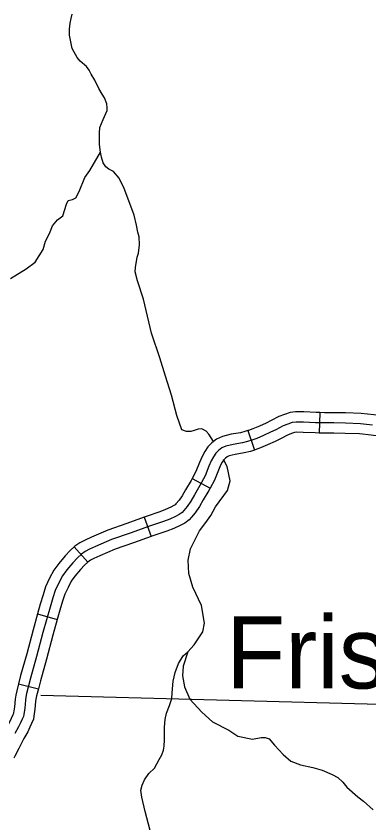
# Model space of a CAD drawing. Extents: x 670147 to 673275, y 705573 to 707613.
# Drawn here: x 672088.3 to 672139.9, y 706307.4 to 706425.4 of the extents above; entities that cross this region are included whole.
import ezdxf

# ---------------------------------------------------------------- set-up
doc = ezdxf.new("R2010")
doc.units = 0
for name, color, linetype in [('25', 7, 'Continuous'), ('32', 7, 'Continuous'), ('35', 7, 'Continuous'), ('5', 7, 'Continuous')]:
    doc.layers.add(name, color=color, linetype=linetype)

msp = doc.modelspace()

# ---------------------------------------------------------------- linework, layer by layer
at = {"layer": '32'}
for p, q in [((672132.75, 706367.45), (672132.66, 706364.45)), ((672122.22, 706364.81), (672123.19, 706361.97)), ((672114.05, 706357.79), (672116.69, 706356.37)), ((672107.06, 706352.14), (672108.06, 706349.31)), ((672096.83, 706347.82), (672098.83, 706345.58)), ((672091.44, 706338), (672094.33, 706337.19)), ((672088.67, 706327.77), (672091.58, 706327.04))]:
    msp.add_line(p, q, dxfattribs=at)
for points in [[(672132.75, 706367.45), (672132.2, 706367.47), (672130.43, 706367.56), (672129.19, 706367.57), (672128.39, 706367.46), (672127.56, 706367.19), (672126.75, 706366.87), (672125.63, 706366.27), (672124.91, 706365.92), (672123.9, 706365.46), (672122.96, 706365.08), (672122.3, 706364.83), (672122.22, 706364.81)], [(672143.39, 706366.76), (672142.99, 706366.8), (672142.06, 706366.91), (672140.66, 706367.1), (672138.79, 706367.32), (672136.52, 706367.41), (672134.82, 706367.43), (672133.44, 706367.43), (672132.75, 706367.45)], [(672140.47, 706365.61), (672138.68, 706365.82), (672136.48, 706365.91), (672134.81, 706365.93), (672133.41, 706365.93), (672132.13, 706365.97), (672130.38, 706366.06), (672129.28, 706366.07), (672128.72, 706365.99), (672128.07, 706365.78), (672127.39, 706365.51), (672126.3, 706364.93), (672125.55, 706364.57), (672124.5, 706364.08), (672123.51, 706363.68), (672122.8, 706363.42), (672122.19, 706363.21), (672121.41, 706363.04), (672120.07, 706362.8), (672119, 706362.54), (672118.42, 706362.28), (672117.94, 706361.92), (672117.54, 706361.49), (672117.18, 706360.98), (672116.87, 706360.4), (672116.53, 706359.59), (672115.96, 706358.18), (672115.21, 706356.79), (672114.39, 706355.42), (672113.88, 706354.5), (672113.33, 706353.69), (672112.83, 706353.14), (672112.59, 706352.85), (672112.19, 706352.56), (672111.65, 706352.27), (672110.78, 706351.87), (672109.87, 706351.51), (672107.82, 706350.82)], [(672122.22, 706364.81), (672121.79, 706364.66), (672121.12, 706364.51), (672119.76, 706364.27), (672118.51, 706363.97), (672117.65, 706363.58), (672116.93, 706363.04), (672116.37, 706362.43), (672115.91, 706361.76), (672115.52, 706361.05), (672115.14, 706360.16), (672114.6, 706358.82), (672114.05, 706357.79)], [(672132.66, 706364.45), (672132.07, 706364.47), (672130.33, 706364.56), (672129.38, 706364.57), (672129.05, 706364.52), (672128.58, 706364.37), (672128.02, 706364.15), (672126.98, 706363.6), (672126.19, 706363.21), (672125.1, 706362.71), (672124.05, 706362.28), (672123.31, 706362.01), (672123.19, 706361.97)], [(672143.07, 706363.78), (672142.66, 706363.82), (672141.68, 706363.93), (672140.28, 706364.13), (672138.56, 706364.33), (672136.45, 706364.41), (672134.81, 706364.43), (672133.39, 706364.43), (672132.66, 706364.45)], [(672123.19, 706361.97), (672122.59, 706361.76), (672121.7, 706361.57), (672120.38, 706361.34), (672119.49, 706361.12), (672119.2, 706360.99), (672118.95, 706360.8), (672118.71, 706360.54), (672118.46, 706360.19), (672118.22, 706359.75), (672117.92, 706359.02), (672117.32, 706357.54), (672116.69, 706356.37)], [(672114.05, 706357.79), (672113.91, 706357.53), (672113.09, 706356.17), (672112.6, 706355.29), (672112.15, 706354.62), (672111.69, 706354.11), (672111.56, 706353.95), (672111.4, 706353.84), (672110.97, 706353.61), (672110.19, 706353.25), (672109.36, 706352.92), (672107.33, 706352.24), (672107.06, 706352.14)], [(672116.69, 706356.37), (672116.52, 706356.05), (672115.69, 706354.67), (672115.16, 706353.72), (672114.52, 706352.77), (672113.97, 706352.16), (672113.63, 706351.74), (672112.98, 706351.28), (672112.32, 706350.93), (672111.37, 706350.49), (672110.38, 706350.1), (672108.31, 706349.4), (672108.06, 706349.31)], [(672107.06, 706352.14), (672104.51, 706351.23), (672101.74, 706350.26), (672099.35, 706349.22), (672098.41, 706348.81), (672097.64, 706348.42), (672096.92, 706347.9), (672096.83, 706347.82)], [(672107.82, 706350.82), (672105.01, 706349.82), (672102.29, 706348.86), (672099.95, 706347.85), (672099.05, 706347.46), (672098.43, 706347.14), (672097.86, 706346.72), (672097.28, 706346.22), (672096.6, 706345.48), (672095.74, 706344.43), (672095.12, 706343.59), (672094.56, 706342.56), (672094.04, 706341.43), (672093.69, 706340.33), (672093.28, 706338.99), (672092.24, 706335.26), (672091.32, 706331.76), (672090.43, 706328.61), (672089.86, 706326.37), (672089.74, 706325.83), (672089.67, 706325.37), (672089.58, 706324.22), (672089.44, 706323.3), (672089.39, 706323.01), (672089.21, 706322.6), (672088.96, 706322.06), (672088.69, 706321.47), (672088.12, 706320.5)], [(672108.06, 706349.31), (672105.51, 706348.4), (672102.83, 706347.47), (672100.55, 706346.47), (672099.69, 706346.1), (672099.21, 706345.86), (672098.8, 706345.55), (672098.83, 706345.58)], [(672096.83, 706347.82), (672096.23, 706347.29), (672095.47, 706346.47), (672094.55, 706345.35), (672093.85, 706344.39), (672093.22, 706343.23), (672092.64, 706341.97), (672092.26, 706340.78), (672091.84, 706339.41), (672091.44, 706338)], [(672098.83, 706345.58), (672098.33, 706345.14), (672097.73, 706344.5), (672096.93, 706343.51), (672096.39, 706342.79), (672095.91, 706341.88), (672095.44, 706340.88), (672095.12, 706339.88), (672094.72, 706338.57), (672094.33, 706337.19)], [(672091.44, 706338), (672090.79, 706335.66), (672089.87, 706332.16), (672088.98, 706329), (672088.67, 706327.77)], [(672094.33, 706337.19), (672093.69, 706334.87), (672092.77, 706331.37), (672091.88, 706328.23), (672091.58, 706327.04)], [(672088.67, 706327.77), (672088.41, 706326.73), (672088.26, 706326.1), (672088.18, 706325.53), (672088.09, 706324.4), (672087.95, 706323.54), (672087.94, 706323.44), (672087.84, 706323.21), (672087.6, 706322.69), (672087.36, 706322.17), (672086.8, 706321.21), (672086.03, 706319.67), (672085.46, 706318.57), (672085.3, 706318.26)], [(672091.58, 706327.04), (672091.32, 706326.02), (672091.21, 706325.55), (672091.17, 706325.2), (672091.07, 706324.05), (672090.92, 706323.06), (672090.84, 706322.59), (672090.58, 706321.99), (672090.32, 706321.43), (672090.02, 706320.77), (672089.44, 706319.79), (672088.71, 706318.31), (672088.13, 706317.2), (672087.97, 706316.89)]]:
    msp.add_lwpolyline(points, dxfattribs=at)
at = {"layer": '35'}
for points in [[(672117.17, 706363.22), (672116.52, 706364.3), (672116.14, 706364.73), (672115.5, 706365.07), (672114.94, 706365.03), (672114.38, 706364.85), (672113.87, 706364.68), (672113.23, 706364.68), (672112.58, 706364.94), (672111.85, 706367.01), (672111.04, 706370.01), (672110.18, 706372.79), (672109.33, 706375.45), (672108.13, 706379.05), (672106.97, 706384.06), (672106.07, 706386.72), (672105.73, 706388.05), (672105.77, 706388.67), (672106.03, 706390.19), (672106.2, 706390.79), (672106.37, 706391.98), (672106.33, 706393.17), (672106.11, 706393.86), (672105.94, 706394.85), (672105.6, 706396.35), (672104.96, 706398.06), (672104.1, 706400.21), (672103.37, 706401.74), (672102.58, 706402.71), (672101.87, 706403.05), (672101.42, 706403.42), (672101.06, 706403.97), (672100.8, 706404.83), (672100.67, 706405.53), (672100.5, 706406.69), (672100.5, 706408.32), (672100.56, 706409.18), (672101.03, 706410.34), (672101.62, 706411.66), (672101.66, 706412.03), (672101.59, 706412.62), (672101.27, 706413.5), (672100.9, 706414.05), (672100.41, 706414.88), (672099.83, 706416.06), (672099.32, 706416.96), (672099, 706417.54), (672098.62, 706418.08), (672097.68, 706418.86), (672097.25, 706419.41), (672096.54, 706420.69), (672096.29, 706421.91), (672096.14, 706422.66), (672096.13, 706423.55), (672096.24, 706424.41), (672096.39, 706425.11), (672096.54, 706425.76)], [(672087.52, 706387.06), (672089.8, 706388.5), (672091.1, 706389.47), (672092.26, 706391.33), (672092.64, 706392.55), (672093.22, 706393.67), (672093.65, 706394.78), (672094.39, 706395.63), (672095.13, 706396.21), (672095.68, 706397.95), (672095.95, 706398.48), (672096.56, 706398.64), (672097.03, 706398.88), (672097.56, 706399.78), (672098.37, 706401.84), (672099.11, 706402.85), (672100.67, 706405.53)], [(672113.46, 706332.46), (672114.38, 706333.49), (672115.62, 706335.38), (672115.88, 706336.62), (672115.45, 706339.23), (672114.17, 706341.93), (672113.57, 706343.9), (672113.5, 706345.85), (672113.81, 706347.54), (672115.14, 706350.15), (672116.05, 706351.36), (672116.78, 706352.39), (672117.5, 706353.67), (672119.26, 706356.03), (672119.62, 706357.49), (672119.2, 706359.55), (672118.66, 706360.58)], [(672107.93, 706306.31), (672107.21, 706309.07), (672106.69, 706311.18), (672106.55, 706312.21), (672106.76, 706312.94), (672107.1, 706313.73), (672107.72, 706314.63), (672108.55, 706315.45), (672108.9, 706316.07), (672109.22, 706316.69), (672109.64, 706317.36), (672109.86, 706318.05), (672109.98, 706318.64), (672110, 706319.58), (672110.02, 706321.43), (672110.1, 706322.55), (672110.31, 706323.5), (672110.77, 706324.58), (672111.1, 706325.64), (672111.13, 706326.45), (672111.28, 706328.14), (672111.57, 706329.44), (672112.06, 706330.73), (672112.74, 706331.87), (672113.46, 706332.46)], [(672113.46, 706332.46), (672112.74, 706330.36), (672112.67, 706328.92), (672112.93, 706327.34), (672113.72, 706325.51), (672115.49, 706323.6), (672117.07, 706322.22), (672119.43, 706320.98), (672120.74, 706320.12), (672122.91, 706319.66), (672124.16, 706319.93), (672124.75, 706319.93), (672125.34, 706319.73), (672126.12, 706318.81), (672127.37, 706317.43), (672128.49, 706316.45), (672129.93, 706315.92), (672131.7, 706315.53), (672133.08, 706315.13), (672134.56, 706314.52), (672135.38, 706314.08), (672136.1, 706313.37), (672136.69, 706312.64), (672138.33, 706311.23), (672139.12, 706310.6), (672140.56, 706309.36)]]:
    msp.add_lwpolyline(points, dxfattribs=at)
at = {"layer": '5'}
msp.add_lwpolyline([(672143.33, 706324.68), (672091.94, 706326.06)], dxfattribs=at)

# ---------------------------------------------------------------- texts
at = {"layer": '25'}
msp.add_text('Frisco', height=10.56, dxfattribs=at).set_placement((672119.05, 706327.09))

doc.saveas('drawing.dxf')
